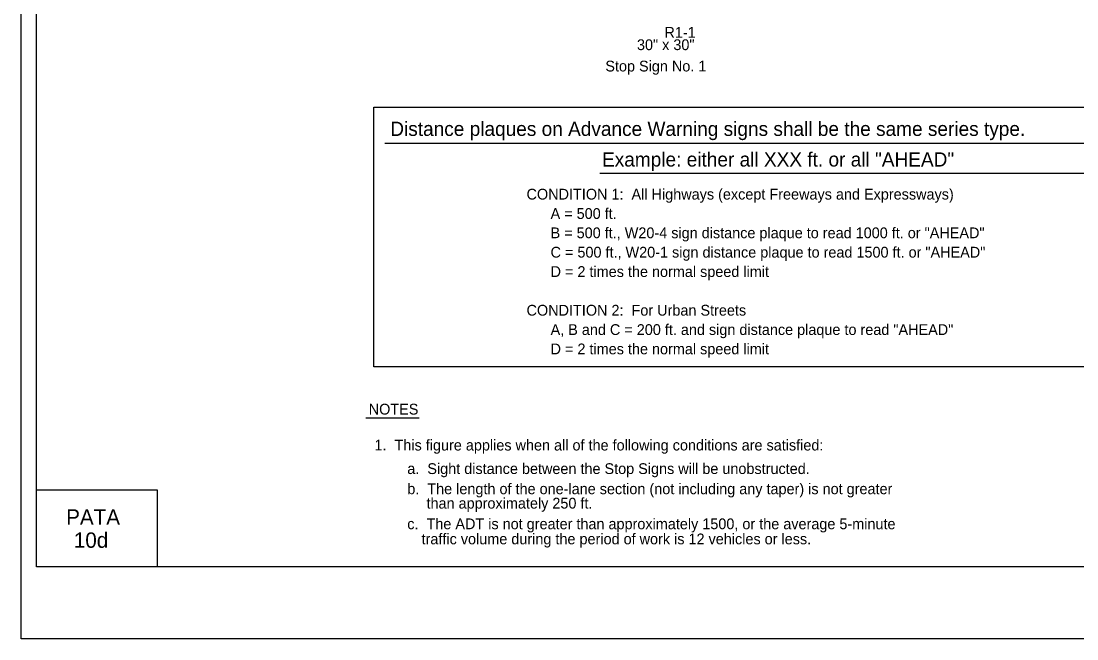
# Model space of a CAD drawing. Extents: x -14145 to -13521, y 30244 to 30661.
# Drawn here: x -13824.17 to -13803.62, y 30505.81 to 30517.84 of the extents above; entities that cross this region are included whole.
import ezdxf

# ---------------------------------------------------------------- set-up
doc = ezdxf.new("R2010")
doc.units = 0
for name, color, linetype in [('1', 7, 'Continuous'), ('10', 7, 'Continuous'), ('2', 7, 'Continuous'), ('4', 7, 'Continuous'), ('61', 7, 'Continuous')]:
    doc.layers.add(name, color=color, linetype=linetype)

msp = doc.modelspace()

# ---------------------------------------------------------------- linework, layer by layer
at = {"layer": '10'}
for p, q in [((-13823.874, 30507.207), (-13823.874, 30529.777)), ((-13823.874, 30508.707), (-13821.524, 30508.707)), ((-13821.524, 30508.707), (-13821.524, 30507.207)), ((-13792.422, 30507.207), (-13823.874, 30507.207))]:
    msp.add_line(p, q, dxfattribs=at)
at = {"layer": '2'}
for p, q in [((-13817.092, 30515.457), (-13797.142, 30515.457)), ((-13812.906, 30514.872), (-13801.469, 30514.872)), ((-13816.426, 30510.103), (-13817.464, 30510.103))]:
    msp.add_line(p, q, dxfattribs=at)
msp.add_lwpolyline([(-13817.305, 30516.159), (-13796.863, 30516.159), (-13796.863, 30511.107), (-13817.305, 30511.107)], close=True, dxfattribs=at)
at = {"layer": '61'}
msp.add_lwpolyline([(-13824.174, 30531.307), (-13791.174, 30531.307), (-13791.174, 30505.807), (-13824.174, 30505.807)], close=True, dxfattribs=at)

# ---------------------------------------------------------------- texts
at = {"layer": '1'}
for s, p in [('CONDITION 1:  All Highways (except Freeways and Expressways)', (-13814.333, 30514.361)), ('      A = 500 ft.', (-13814.333, 30513.984)), ('      B = 500 ft., W20-4 sign distance plaque to read 1000 ft. or "AHEAD"', (-13814.333, 30513.608)), ('      C = 500 ft., W20-1 sign distance plaque to read 1500 ft. or "AHEAD"', (-13814.333, 30513.231)), ('      D = 2 times the normal speed limit', (-13814.333, 30512.854)), ('CONDITION 2:  For Urban Streets', (-13814.333, 30512.101)), ('      A, B and C = 200 ft. and sign distance plaque to read "AHEAD"', (-13814.333, 30511.724)), ('      D = 2 times the normal speed limit', (-13814.333, 30511.348))]:
    msp.add_text(s, height=0.21, dxfattribs=at).set_placement(p)
at = {"layer": '2'}
for s, height, p in [('R1-1', 0.21, (-13811.648, 30517.512)), ('30" x 30"', 0.21, (-13812.183, 30517.271)), ('Stop Sign No. 1', 0.21, (-13812.799, 30516.855)), ('Distance plaques on Advance Warning signs shall be the same series type.', 0.2772, (-13816.986, 30515.6)), ('Example: either all XXX ft. or all "AHEAD"', 0.2772, (-13812.863, 30515.004)), ('NOTES', 0.21, (-13817.406, 30510.175)), ('1.  This figure applies when all of the following conditions are satisfied:', 0.21, (-13817.294, 30509.475)), ('a.  Sight distance between the Stop Signs will be unobstructed.', 0.21, (-13816.655, 30509.017)), ('b.  The length of the one-lane section (not including any taper) is not greater', 0.21, (-13816.655, 30508.624)), ('   than approximately 250 ft.', 0.21, (-13816.515, 30508.344)), ('c.  The ADT is not greater than approximately 1500, or the average 5-minute', 0.21, (-13816.655, 30507.942)), ('    traffic volume during the period of work is 12 vehicles or less.', 0.21, (-13816.689, 30507.648))]:
    msp.add_text(s, height=height, dxfattribs=at).set_placement(p)
at = {"layer": '4'}
for s, p in [('PATA', (-13823.296, 30508.03)), ('10d', (-13823.147, 30507.58))]:
    msp.add_text(s, height=0.3, dxfattribs=at).set_placement(p)

doc.saveas('drawing.dxf')
